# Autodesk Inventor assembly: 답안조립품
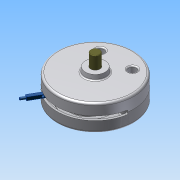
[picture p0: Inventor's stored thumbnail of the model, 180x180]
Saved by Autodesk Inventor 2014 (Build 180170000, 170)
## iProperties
Created: 2015-06
Part Number: 답안조립품
Document SubType Name: Assembly
Designer: Administrator
Author: Administrator
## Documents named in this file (10)
- C:\Documents and Settings\Administrator\바탕 화면\450631V1006\답안조립품.iam
- C:\Documents and Settings\Administrator\바탕 화면\450631V1006\1-본체.ipt
- C:\Documents and Settings\Administrator\바탕 화면\450631V1006\베어링62_22.ipt
- C:\Documents and Settings\Administrator\바탕 화면\450631V1006\덮개.ipt
- C:\Documents and Settings\Administrator\바탕 화면\450631V1006\축.ipt
- C:\Documents and Settings\Administrator\바탕 화면\450631V1006\멈춤링.ipt
- C:\Documents and Settings\Administrator\바탕 화면\450631V1006\슬라이더2.ipt
- C:\Documents and Settings\Administrator\바탕 화면\450631V1006\슬라이더.ipt
- C:\Documents and Settings\Administrator\바탕 화면\450631V1006\평행핀.ipt
- C:\Documents and Settings\Administrator\바탕 화면\450631V1006\M10x35.ipt
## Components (8 placed, 5 different names)
1. 1-본체:1
2. KS B 2023 62/22 - 22 x 50 x 14:1
3. KS B 2023 62/22 - 22 x 50 x 14:2
4. KS B 1336 22 x 1.2:1
5. KS B 1336 22 x 1.2:2
6. KS B 1320 B B 5 x  20:1
7. KS B 1003 - 미터 M 10 x 35:1
8. KS B 1003 - 미터 M 10 x 35:2
